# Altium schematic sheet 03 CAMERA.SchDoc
size 386 x 246 mm
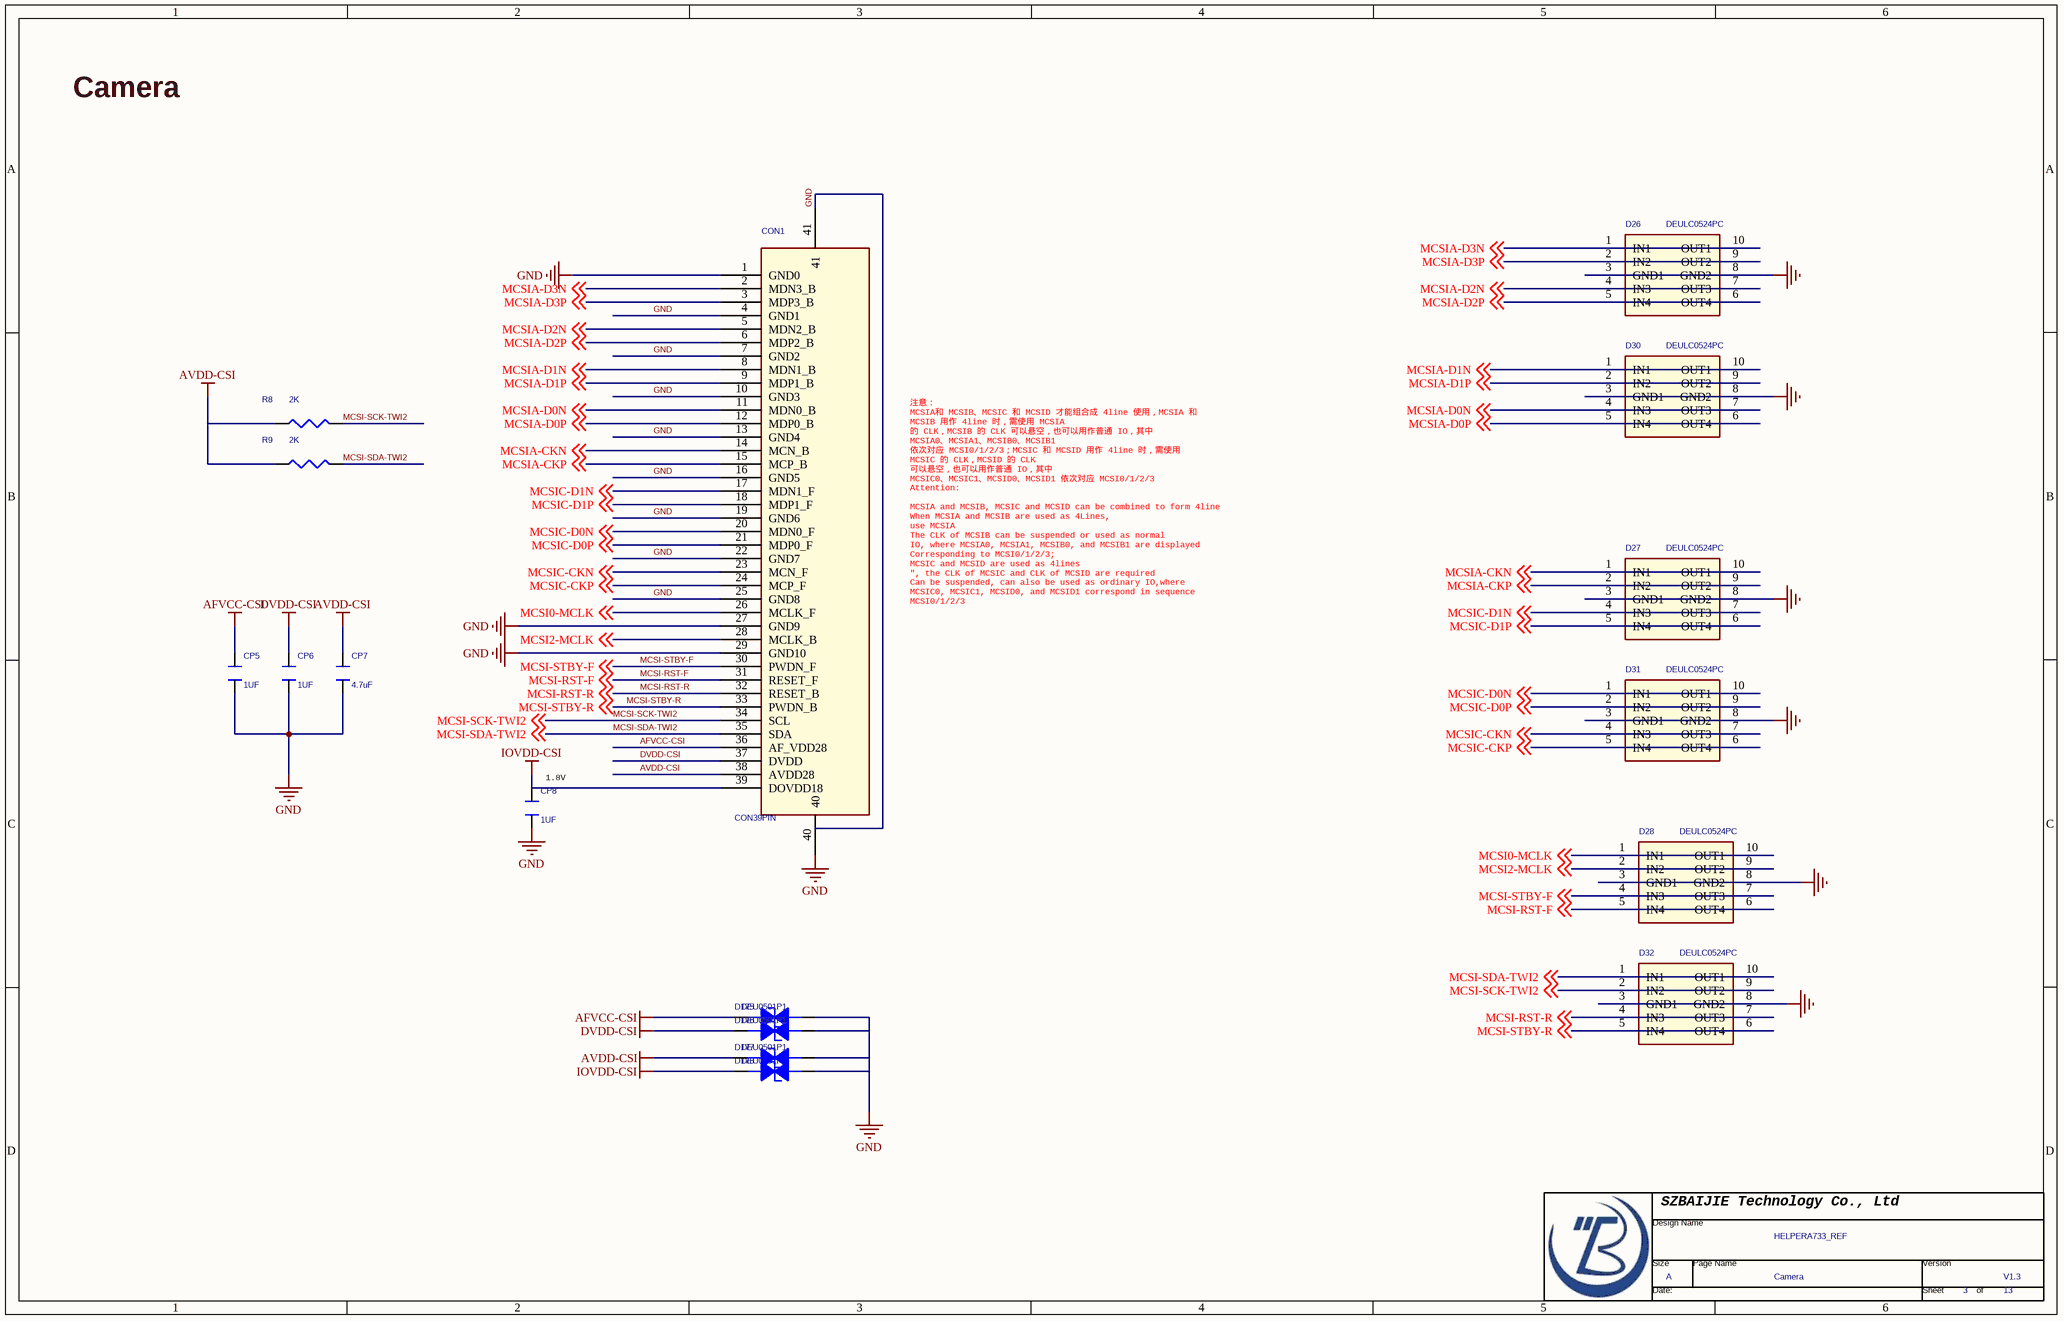
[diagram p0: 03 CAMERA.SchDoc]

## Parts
*  Page Count: 13  Page Number: 3  Page Size: A  Title: HELPERA733_REF  RevCode: V1.3  Doc: Camera  (hidden comment: TitleBlock0-BJ)  (graphical)
CON1  CON39PIN  [FH35C-39S-0.3SHW]
CP5  1UF  [C0603]
CP6  1UF  [C0603]
CP7  4.7uF  [C0603]
CP8  1UF  [C0603]
D26  DEULC0524PC  [DFN2510-10_L2.5-W1.0-P0.50-BL]
D27  DEULC0524PC  [DFN2510-10_L2.5-W1.0-P0.50-BL]
D28  DEULC0524PC  [DFN2510-10_L2.5-W1.0-P0.50-BL]
D30  DEULC0524PC  [DFN2510-10_L2.5-W1.0-P0.50-BL]
D31  DEULC0524PC  [DFN2510-10_L2.5-W1.0-P0.50-BL]
D32  DEULC0524PC  [DFN2510-10_L2.5-W1.0-P0.50-BL]
D175  DEU0501P1  [ESD0402]
D176  DEU0501P1  [ESD0402]
D177  DEU0501P1  [ESD0402]
D178  DEU0501P1  [ESD0402]
R8  2K  [R0402]
R9  2K  [R0402]

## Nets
AFVCC-CSI: CON1.36(AF_VDD28) CP5.1 D175.2(CATHODE)
AVDD-CSI: CON1.38(AVDD28) CP7.1 D177.2(CATHODE) R8.1 R9.1
DVDD-CSI: CON1.37(DVDD) CP6.1 D176.2(CATHODE)
GND: CON1.1(GND0) CON1.4(GND1) CON1.7(GND2) CON1.10(GND3) CON1.13(GND4) CON1.16(GND5) CON1.19(GND6) CON1.22(GND7) CON1.25(GND8) CON1.27(GND9) CON1.29(GND10) CON1.40 CON1.41 CP5.2 CP6.2 CP7.2 CP8.2 D26.3(GND1) D26.8(GND2) D27.3(GND1) D27.8(GND2) D28.3(GND1) D28.8(GND2) D30.3(GND1) D30.8(GND2) D31.3(GND1) D31.8(GND2) D32.3(GND1) D32.8(GND2) D175.1(ANODE) D176.1(ANODE) D177.1(ANODE) D178.1(ANODE)
IOVDD-CSI: CON1.39(DOVDD18) CP8.1 D178.2(CATHODE)
MCSI0-MCLK: CON1.26(MCLK_F) D28.1(IN1) D28.10(OUT1) ; off-sheet MCSI0-MCLK
MCSI2-MCLK: CON1.28(MCLK_B) D28.2(IN2) D28.9(OUT2) ; off-sheet MCSI2-MCLK
MCSI-RST-F: CON1.31(RESET_F) D28.5(IN4) D28.6(OUT4) ; off-sheet MCSI-RST-F
MCSI-RST-R: CON1.32(RESET_B) D32.4(IN3) D32.7(OUT3) ; off-sheet MCSI-RST-R
MCSI-SCK-TWI2: CON1.34(SCL) D32.2(IN2) D32.9(OUT2) R8.2 ; off-sheet MCSI-SCK-TWI2
MCSI-SDA-TWI2: CON1.35(SDA) D32.1(IN1) D32.10(OUT1) R9.2 ; off-sheet MCSI-SDA-TWI2
MCSI-STBY-F: CON1.30(PWDN_F) D28.4(IN3) D28.7(OUT3) ; off-sheet MCSI-STBY-F
MCSI-STBY-R: CON1.33(PWDN_B) D32.5(IN4) D32.6(OUT4) ; off-sheet MCSI-STBY-R
MCSIA-CKN: CON1.14(MCN_B) D27.1(IN1) D27.10(OUT1) ; off-sheet MCSIA-CKN
MCSIA-CKP: CON1.15(MCP_B) D27.2(IN2) D27.9(OUT2) ; off-sheet MCSIA-CKP
MCSIA-D0N: CON1.11(MDN0_B) D30.4(IN3) D30.7(OUT3) ; off-sheet MCSIA-D0N
MCSIA-D0P: CON1.12(MDP0_B) D30.5(IN4) D30.6(OUT4) ; off-sheet MCSIA-D0P
MCSIA-D1N: CON1.8(MDN1_B) D30.1(IN1) D30.10(OUT1) ; off-sheet MCSIA-D1N
MCSIA-D1P: CON1.9(MDP1_B) D30.2(IN2) D30.9(OUT2) ; off-sheet MCSIA-D1P
MCSIA-D2N: CON1.5(MDN2_B) D26.4(IN3) D26.7(OUT3) ; off-sheet MCSIA-D2N
MCSIA-D2P: CON1.6(MDP2_B) D26.5(IN4) D26.6(OUT4) ; off-sheet MCSIA-D2P
MCSIA-D3N: CON1.2(MDN3_B) D26.1(IN1) D26.10(OUT1) ; off-sheet MCSIA-D3N
MCSIA-D3P: CON1.3(MDP3_B) D26.2(IN2) D26.9(OUT2) ; off-sheet MCSIA-D3P
MCSIC-CKN: CON1.23(MCN_F) D31.4(IN3) D31.7(OUT3) ; off-sheet MCSIC-CKN
MCSIC-CKP: CON1.24(MCP_F) D31.5(IN4) D31.6(OUT4) ; off-sheet MCSIC-CKP
MCSIC-D0N: CON1.20(MDN0_F) D31.1(IN1) D31.10(OUT1) ; off-sheet MCSIC-D0N
MCSIC-D0P: CON1.21(MDP0_F) D31.2(IN2) D31.9(OUT2) ; off-sheet MCSIC-D0P
MCSIC-D1N: CON1.17(MDN1_F) D27.4(IN3) D27.7(OUT3) ; off-sheet MCSIC-D1N
MCSIC-D1P: CON1.18(MDP1_F) D27.5(IN4) D27.6(OUT4) ; off-sheet MCSIC-D1P

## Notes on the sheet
- Camera
- 注意：
  MCSIA和 MCSIB、MCSIC 和 MCSID 才能组合成 4line 使用，MCSIA 和
  MCSIB 用作 4line 时，需使用 MCSIA
  的 CLK，MCSIB 的 CLK 可以悬空，也可以用作普通 IO，其中
  MCSIA0、MCSIA1、MCSIB0、MCSIB1
  依次对应 MCSI0/1/2/3；MCSIC 和 MCSID 用作 4line 时，需使用
  MCSIC 的 CLK，MCSID 的 CLK
  可以悬空，也可以用作普通 IO，其中
  MCSIC0、MCSIC1、MCSID0、MCSID1 依次对应 MCSI0/1/2/3
  Attention:
  MCSIA and MCSIB, MCSIC and MCSID can be combined to form 4line
  When MCSIA and MCSIB are used as 4Lines,
  use MCSIA
  The CLK of MCSIB can be suspended or used as normal
  IO, where MCSIA0, MCSIA1, MCSIB0, and MCSIB1 are displayed
  Corresponding to MCSI0/1/2/3;
  MCSIC and MCSID are used as 4lines
  ", the CLK of MCSIC and CLK of MCSID are required
  Can be suspended, can also be used as ordinary IO,where
  MCSIC0, MCSIC1, MCSID0, and MCSID1 correspond in sequence
  MCSI0/1/2/3
- (near CP8) 1.8V

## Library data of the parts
CON1 = CON39PIN_0
CP5-CP8 = C-C0603-X5R_1: Parameter: C0402-X5R
D26-D28 D30-D32 = rRClamp0524P
D175-D178 = 1_1.5KE100A_Dup1: 1ST PART DESCRIPTION: WILL ESD9B5V Bidirection ESD Protection
R8 R9 = R-R0402-1%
